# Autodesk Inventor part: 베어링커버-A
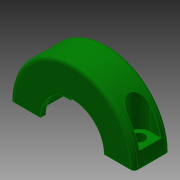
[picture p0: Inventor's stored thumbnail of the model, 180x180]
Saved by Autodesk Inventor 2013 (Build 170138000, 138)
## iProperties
Created: 2018-01
Part Number: 베어링커버-A
Material: 알루미늄 6061
Document SubType Name: Modeling
Designer: mduedu
Density: 2.71 g/cm^3
Mass: 7.15169 g
Surface Area: 19.8517 cm^2
Volume: 2.639 cm^3
Author: mduedu
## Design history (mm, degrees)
sketch "스케치1"
  geometry: L1 (-17.5, 0)-(17.5, 0); A1 r 17.5 centre (0, 0) between (-17.5, 0) and (17.5, 0); 2 further points
  constraints: 2 coincident, 2 end point, 2 point on circle, 1 centre point, 1 horizontal, 1 midpoint
  dimensions: "d0" = 35 diameter of A1
extrude "돌출1" new body sketch "스케치1" stored distance "d1" = 10; taper "d2" = 0 deg
sketch "스케치2"
  geometry: C1 r 11 at (0, 0); C2 r 9 at (0, 0); 1 further point
  constraints: 2 centre point, 2 coincident
  dimensions: "d3" = 22 diameter of C1; "d4" = 18 diameter of C2
extrude "돌출2" cut sketch "스케치2" stored distance "d5" = 7; taper "d6" = 0 deg
extrude "돌출3" cut sketch "스케치2" stored distance "d7" = 7; taper "d8" = 0 deg
fillet "모깎기1" dims "d9" = 0.3
fillet "모깎기2" dims "d10" = 1
node "작업 평면1"
sketch "스케치3"
  geometry: L1 (-15.5, -3.5)-(33.5, -3.5) reference; L2 (-5, -6.5)-(-8.037, -6.5); L3 (-8.037, -6.5)-(-8.037, -0.5); L4 (-8.037, -0.5)-(-5, -0.5); L5 (-0.924, -7)-(0.938, -7) reference; L6 (0.938, -7)-(0.938, -8.5) reference; L7 (0.938, -8.5)-(-7.008, -8.5) reference; L8 (-8.037, -7.5)-(-8.037, 0.5) reference; L9 (-7.008, 1.5)-(0.938, 1.5) reference; L10 (0.938, 1.5)-(0.938, 0) reference; L11 (0.938, 0)-(-0.924, 0) reference; L12 (-1.247, -0.3)-(-1.247, -6.7) reference; L13 (19.247, -6.7)-(19.247, -0.3) reference; L14 (18.924, 0)-(17.062, 0) reference; L15 (17.062, 0)-(17.062, 1.5) reference; L16 (17.062, 1.5)-(25.008, 1.5) reference; L17 (26.037, 0.5)-(26.037, -7.5) reference; L18 (25.008, -8.5)-(17.062, -8.5) reference; L19 (17.062, -8.5)-(17.062, -7) reference; L20 (17.062, -7)-(18.924, -7) reference; A1 r 3 centre (-5, -3.5) between (-5, -6.5) and (-5, -0.5); 1 further point
  constraints: 6 end point, 2 point on circle, 2 tangent, 1 centre point, 1 collinear, 1 horizontal, 1 parallel, 1 perpendicular, 1 point on line, 8 other
  dimensions: "d12" = 6 distance between parallel lines of L4 L2; "d28" = 14 distance of point (9, -3.5) A1.centre
extrude "돌출4" cut sketch "스케치3" stored distance "d15" = 0; taper "d16" = 0 deg
sketch "스케치4"
  geometry: 7 further points
  constraints: 4 vertical alignment, 2 horizontal alignment
sketch "스케치5"
  geometry: L1 (-26.5, -0.5)-(-26.5, 7.5) reference; L2 (-18, 8.5)-(-25.5, 8.5) reference; 2 further points
  constraints: 1 horizontal alignment
  dimensions: "d25" = 3.5 distance from line of point (-23, 3.5) L1; "d26" = 28 distance of point (5, 3.5) point (-23, 3.5); "d27" = 5 distance from line of L2 point (-23, 3.5)
hole "구멍1" sketch "스케치5" at (-23, 3.5), (5, 3.5) diameter "d17" = 3.4; stored, may be unused: countersink angle "d21" = 90 deg, drill point angle "d23" = 0 deg; dims "d18" = 6, "d19" = 4, "d20" = 2, "d22" = 8
fillet "모깎기3" dims "d24" = 0.1
node "솔리드1"
mirror "대칭1"
node "절단 모서리 투영1"
other parameters: "d11" = -4
